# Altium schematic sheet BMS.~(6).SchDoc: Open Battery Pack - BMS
size A3; Date: 26/03/2019; Author: Morgane Vallée - Samuel Lesueur; Revision: 1.0; SheetNumber: 1; SheetTotal: 5
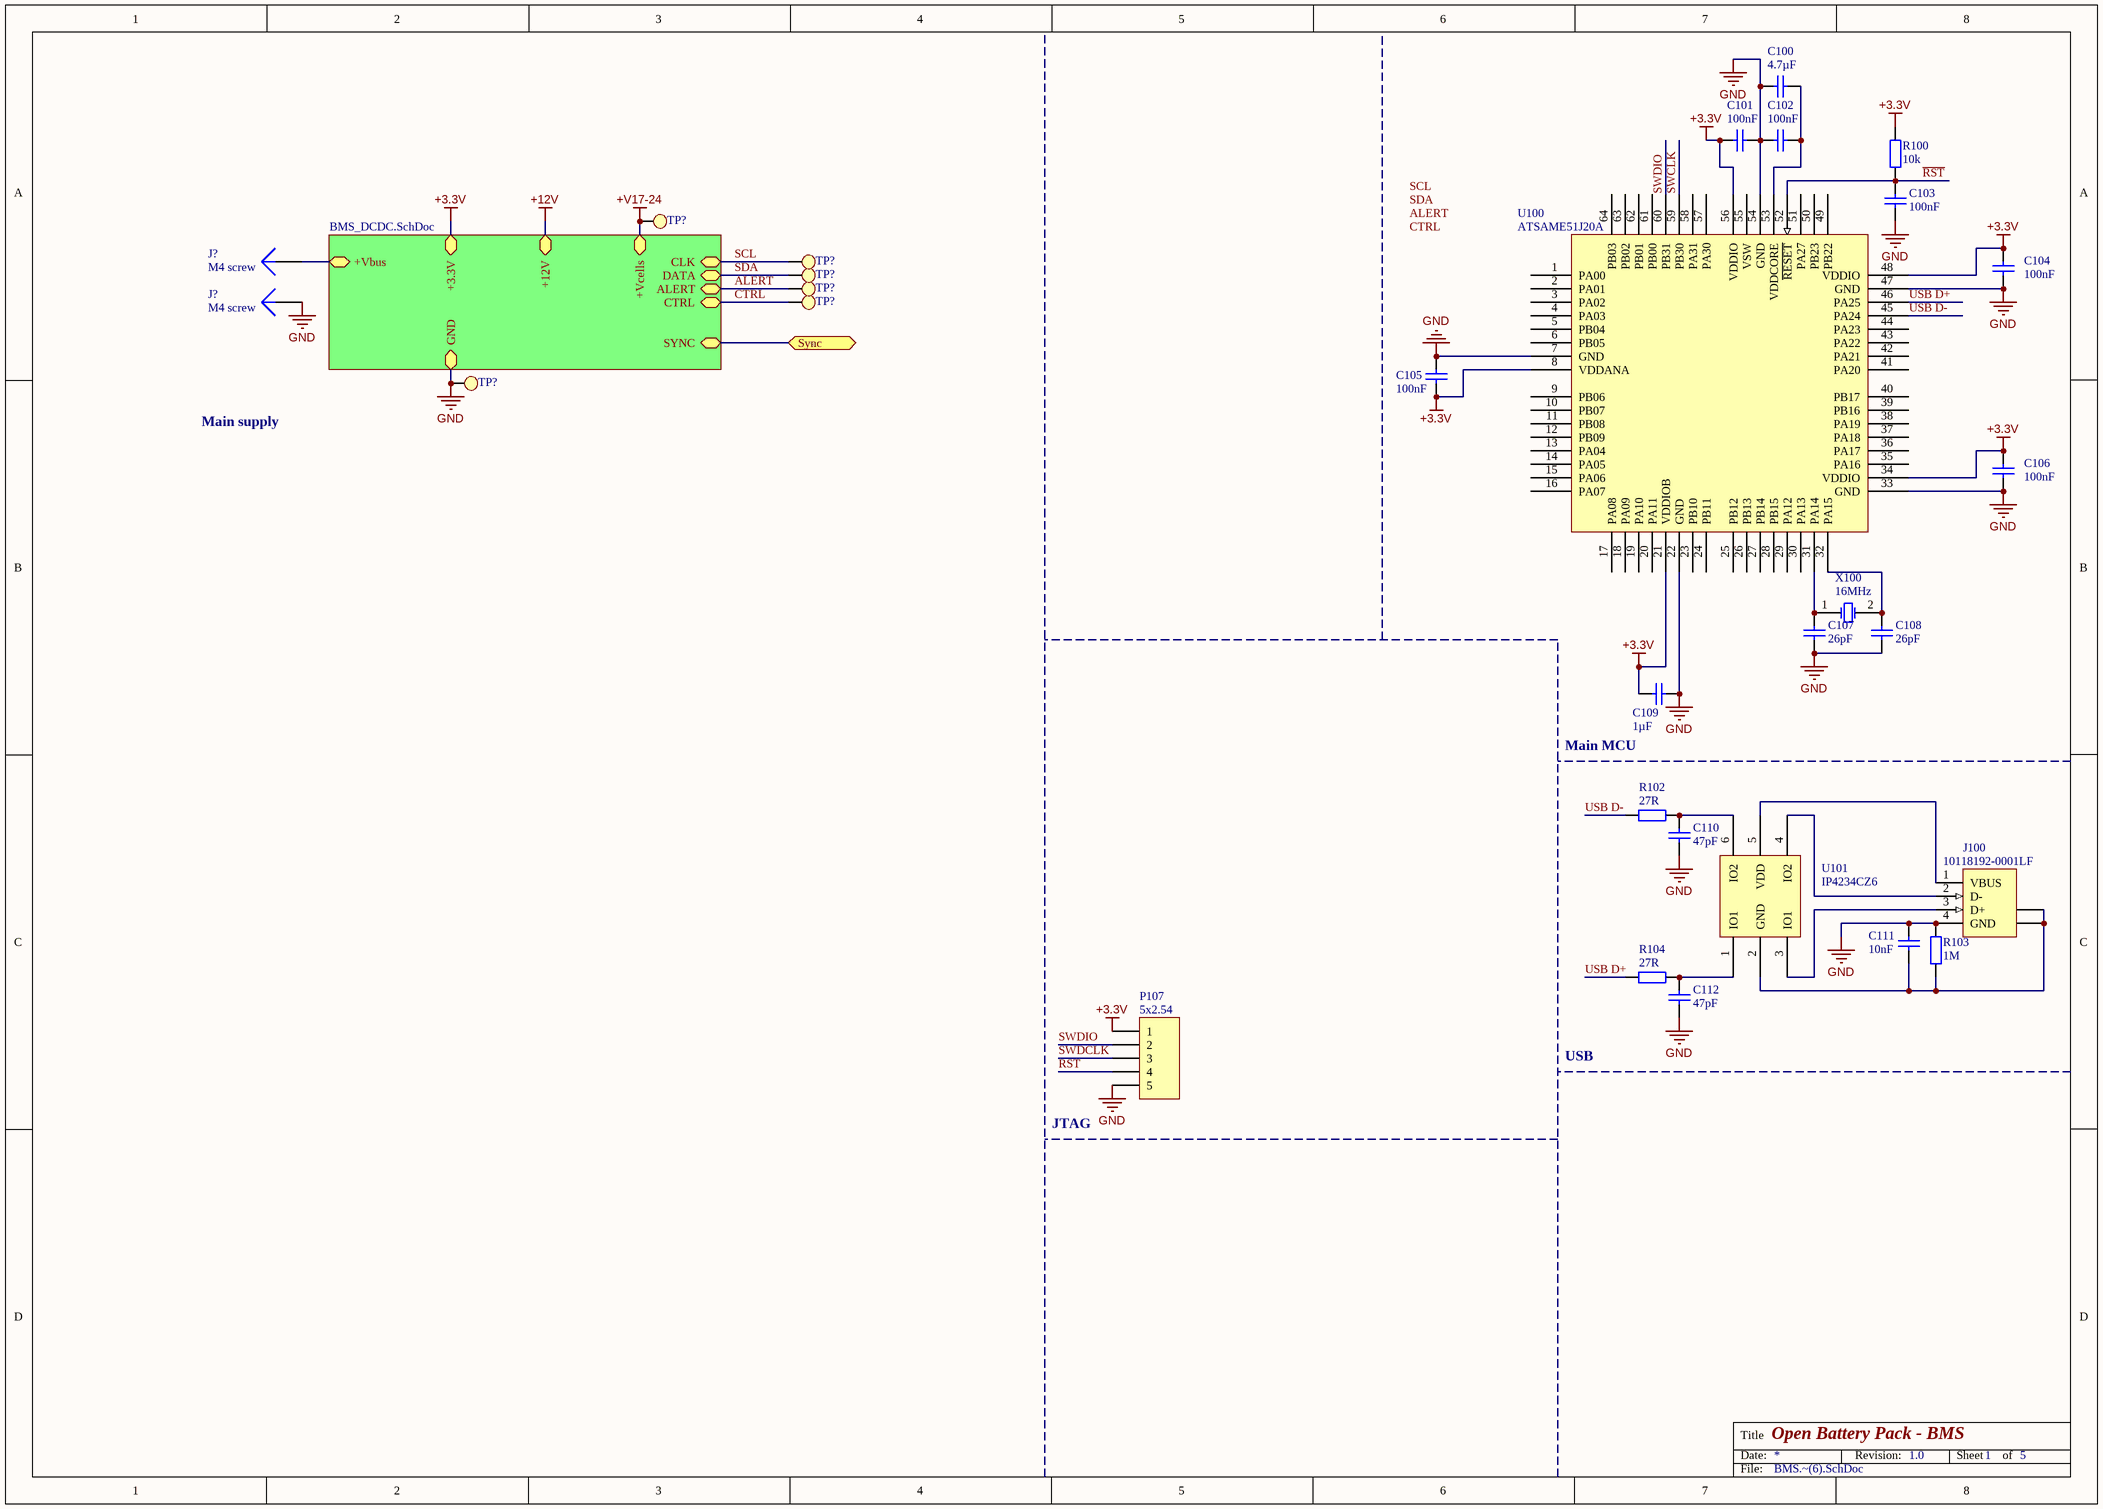
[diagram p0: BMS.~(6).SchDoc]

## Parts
(Parts that share a designator on the sheet are numbered #1, #2 ... from top to bottom, then left to right.)
C100  4.7µF  [C0603]
C101  100nF  [C0603]
C102  100nF  [C0603]
C103  100nF  [C0603]
C104  100nF  [C0603]
C105  100nF  [C0603]
C106  100nF  [C0603]
C107  26pF  [C0603]
C108  26pF  [C0603]
C109  1µF  [C0603]
C110  47pF  [C0603]
C111  10nF  [C0603]
C112  47pF  [C0603]
J100  10118192-0001LF  [FCI USB 10118193-0001LF]
J?#1  M4 screw  [HOLE_4]
J?#2  M4 screw  [HOLE_4]
P107  5x2.54  [HDR1X5]
R100  10k  [R0603]
R102  27R  [R0603]
R103  1M  [R0603]
R104  27R  [R0603]
TP?#1  Test Point  [Test Point]  (value not drawn)
TP?#2  Test Point  [Test Point]  (value not drawn)
TP?#3  Test Point  [Test Point]  (value not drawn)
TP?#4  Test Point  [Test Point]  (value not drawn)
TP?#5  Test Point  [Test Point]  (value not drawn)
TP?#6  Test Point  [Test Point]  (value not drawn)
U100  ATSAME51J20A  [TQFP-64N]
U101  IP4234CZ6  [VISHAY TSOP-6 MO-193C]
X100  16MHz  [ABRACON ABLS]

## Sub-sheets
? = BMS_DCDC.SchDoc: CTRL (bidir), SYNC (bidir), CLK (bidir), DATA (bidir), ALERT (bidir), GND, +3.3V, +Vbus, +Vcells, +12V

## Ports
Sync

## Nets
+3.3V: C101.2 C104.2 C105.1 C106.2 C109.2 P107.1 R100.2 U100.8(VDDANA) U100.21(VDDIOB) U100.34(VDDIO) U100.48(VDDIO) U100.56(VDDIO) ; sheet /+3.3V
+V17-24: TP?#1.1 ; sheet /+Vcells
GND: C100.2 C101.1 C102.2 C103.1 C104.1 C105.2 C106.1 C107.1 C108.1 C109.1 C110.1 C111.2 C112.1 J100.4(GND) J?#2.1 P107.5 R103.1 TP?#6.1 U100.7(GND) U100.22(GND) U100.33(GND) U100.47(GND) U100.54(GND) ; sheet /GND
ALERT: TP?#4.1 ; sheet /ALERT
CTRL: TP?#5.1 ; sheet /CTRL
~{RST}: C103.2 P107.4 R100.1 U100.52(~{RESET})
SCL: TP?#2.1 ; sheet /CLK
SDA: TP?#3.1 ; sheet /DATA
SWCLK: U100.59(PB30)
SWDCLK: P107.3
SWDIO: P107.2 U100.60(PB31)
Sync: port Sync, sheet /SYNC
USB D+: R104.1 U100.46(PA25)
USB D-: R102.1 U100.45(PA24)
NetC100_1: C100.1 C102.1 U100.53(VDDCORE)
NetC107_2: C107.2 U100.31(PA14) X100.1(OSC1)
NetC108_2: C108.2 U100.32(PA15) X100.2(OSC2)
NetC110_2: C110.2 R102.2 U101.6(IO2)
NetC111_1: C111.1 J100.5(SHLD) J100.6(SHLD) R103.2 U101.2(GND)
NetC112_2: C112.2 R104.2 U101.1(IO1)
NetJ100_1: J100.1(VBUS) U101.5(VDD)
NetJ100_2: J100.2(D-) U101.4(IO2)
NetJ100_3: J100.3(D+) U101.3(IO1)
NetJ?#1_1: J?#1.1 ; sheet /+Vbus

Not connected (* = marked no-connect by the designer): U100 1(PA00) 2(PA01) 3(PA02) 4(PA03) 5(PB04) 6(PB05) 9(PB06) 10(PB07) 11(PB08) 12(PB09) 13(PA04) 14(PA05) 15(PA06) 16(PA07) 17(PA08) 18(PA09) 19(PA10) 20(PA11) 23(PB10) 24(PB11) 25(PB12) 26(PB13) 27(PB14) 28(PB15) 29(PA12) 30(PA13) 35(PA16) 36(PA17) 37(PA18) 38(PA19) 39(PB16) 40(PB17) 41(PA20) 42(PA21) 43(PA22) 44(PA23) 49(PB22) 50(PB23) 51(PA27) 55(VSW) 57(PA30) 58(PA31) 61(PB00) 62(PB01) 63(PB02) 64(PB03)

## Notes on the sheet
- Main supply
- Main MCU
- JTAG
- USB
- Labels drawn without touching a wire or pin: ALERT, CTRL, SCL, SDA

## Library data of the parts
C100-C112 = Cap: Capacitor
J100 = 1-353576-1: USB 1.1, Right Angle, SMT, A Type, Receptacle, 4 Position, White; pin to pad: 4>5 5>S 6>S
J?#1 J?#2 = Plug
P107 = Header 5: Header, 5-Pin
R100 R102-R104 = Res2: Resistor
U101 = IP4234CZ6: Single USB 2.0 ESD protection to IEC 61000-4-2 level 4
X100 = XTAL: Crystal Oscillator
